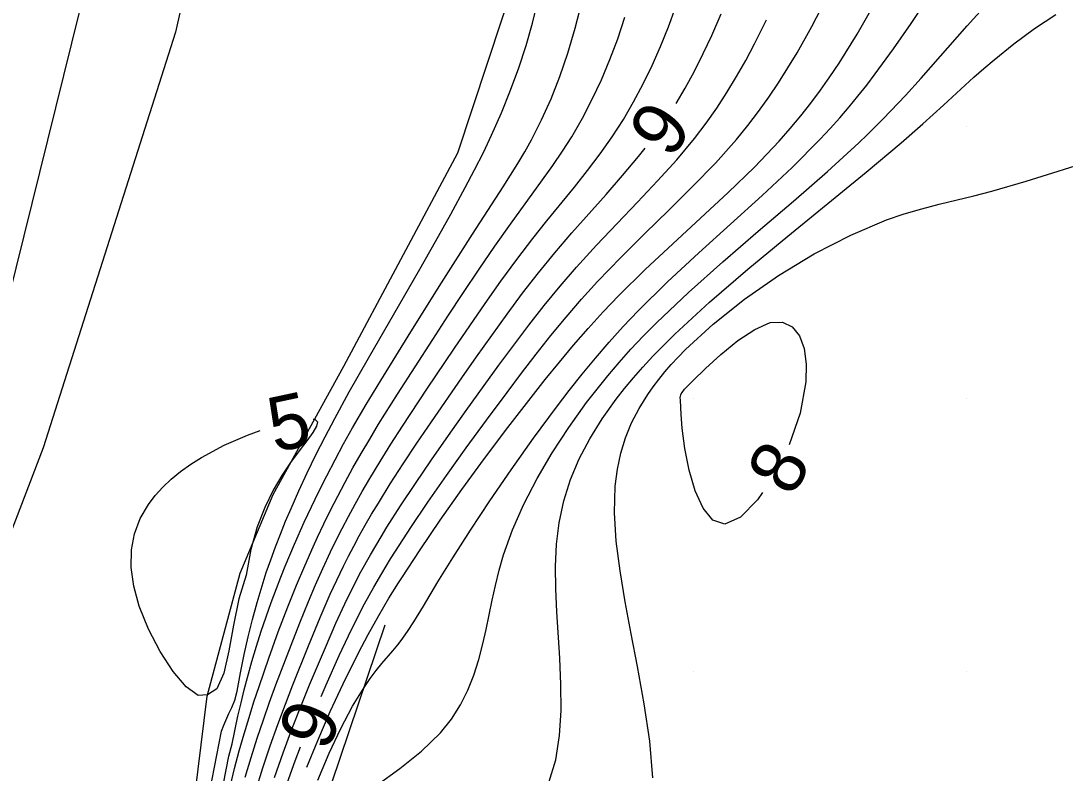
# Model space of a CAD drawing. Extents: x 2602990 to 2605851, y 618069 to 619180.
# Drawn here: x 2603415.29 to 2603453.62, y 618546.27 to 618573.87 of the extents above; entities that cross this region are included whole.
import ezdxf

# ---------------------------------------------------------------- set-up
doc = ezdxf.new("R2010")
doc.units = 0
for name, color, linetype in [('DTM Contours Major', 7, 'Continuous'), ('DTM Contours Major Text', 7, 'Continuous'), ('DTM Contours Minor', 7, 'Continuous'), ('DTM Contours Minor Text', 7, 'Continuous'), ('Exist DTM Crownline', 7, 'Continuous'), ('Exist DTM QL2 LIDAR Elevation Point', 7, 'Continuous'), ('Exist Roads EOP', 7, 'Continuous'), ('PH Exist DTM Breakline', 7, 'Continuous'), ('PH Exist DTM Obscure Area', 7, 'Continuous')]:
    doc.layers.add(name, color=color, linetype=linetype)

msp = doc.modelspace()

# ---------------------------------------------------------------- linework, layer by layer
at = {"layer": 'DTM Contours Major'}
for points in [[(2603439.345, 618570.846), (2603439.676, 618571.405), (2603440.018, 618572.033), (2603440.342, 618572.676), (2603440.652, 618573.336), (2603440.998, 618574.125)], [(2603423.915, 618545.634), (2603424.177, 618546.464), (2603424.449, 618547.269), (2603424.727, 618548.047), (2603425.006, 618548.793), (2603425.281, 618549.505), (2603425.849, 618550.933), (2603426.28, 618551.979), (2603426.65, 618552.831), (2603426.886, 618553.346), (2603427.136, 618553.864), (2603427.319, 618554.226), (2603427.512, 618554.597), (2603427.717, 618554.976), (2603427.936, 618555.365), (2603428.168, 618555.766), (2603428.416, 618556.18), (2603428.853, 618556.881), (2603429.327, 618557.614), (2603429.833, 618558.375), (2603430.364, 618559.158), (2603431.477, 618560.768), (2603432.023, 618561.549), (2603432.576, 618562.33), (2603433.139, 618563.107), (2603433.712, 618563.875), (2603434.297, 618564.629), (2603434.895, 618565.364), (2603435.519, 618566.092), (2603436.772, 618567.502), (2603437.38, 618568.197), (2603437.962, 618568.893), (2603438.204, 618569.205)]]:
    msp.add_lwpolyline(points, dxfattribs=at)
at = {"layer": 'DTM Contours Minor'}
for points in [[(2603421.36, 618538.867), (2603422.93, 618546.892), (2603423.048, 618547.34), (2603423.263, 618548.355), (2603423.376, 618548.845), (2603423.494, 618549.32), (2603423.615, 618549.783), (2603423.777, 618550.362), (2603423.944, 618550.925), (2603424.118, 618551.472), (2603424.298, 618552.007), (2603424.483, 618552.532), (2603424.675, 618553.047), (2603424.833, 618553.455), (2603424.995, 618553.86), (2603425.333, 618554.665), (2603425.695, 618555.474), (2603425.958, 618556.037), (2603426.234, 618556.607), (2603426.523, 618557.182), (2603426.825, 618557.763), (2603427.141, 618558.347), (2603427.47, 618558.936), (2603427.972, 618559.799), (2603428.504, 618560.681), (2603429.608, 618562.464), (2603430.737, 618564.26), (2603431.876, 618566.045), (2603432.997, 618567.777), (2603433.27, 618568.207), (2603433.534, 618568.636), (2603433.789, 618569.067), (2603434.033, 618569.505), (2603434.409, 618570.242), (2603434.756, 618571.014), (2603435.077, 618571.828), (2603435.372, 618572.691), (2603435.645, 618573.611), (2603435.896, 618574.596)], [(2603421.797, 618543.406), (2603422.659, 618547.806), (2603422.739, 618548.027), (2603422.926, 618548.451), (2603423.035, 618548.679), (2603423.151, 618548.943), (2603423.237, 618549.274), (2603423.357, 618549.954), (2603423.49, 618550.62), (2603423.635, 618551.271), (2603423.793, 618551.908), (2603423.963, 618552.532), (2603424.146, 618553.143), (2603424.303, 618553.625), (2603424.467, 618554.101), (2603424.64, 618554.572), (2603424.822, 618555.042), (2603425.012, 618555.51), (2603425.211, 618555.979), (2603425.5, 618556.629), (2603425.805, 618557.284), (2603426.126, 618557.944), (2603426.463, 618558.61), (2603426.815, 618559.281), (2603427.348, 618560.26), (2603428.048, 618561.495), (2603429.937, 618564.761), (2603430.514, 618565.771), (2603431.075, 618566.774), (2603431.608, 618567.755), (2603431.949, 618568.402), (2603432.271, 618569.039), (2603432.574, 618569.673), (2603432.939, 618570.5), (2603433.272, 618571.328), (2603433.572, 618572.154), (2603433.839, 618572.975), (2603434.073, 618573.787), (2603434.274, 618574.586)], [(2603425.792, 618546.485), (2603426.189, 618547.468), (2603426.648, 618548.525), (2603427.12, 618549.541), (2603427.686, 618550.677), (2603428.046, 618551.357), (2603428.434, 618552.053), (2603428.806, 618552.683), (2603429.151, 618553.245), (2603429.272, 618553.436), (2603429.945, 618554.468), (2603430.687, 618555.554), (2603431.481, 618556.675), (2603432.314, 618557.812), (2603433.168, 618558.946), (2603434.028, 618560.057), (2603434.544, 618560.708), (2603435.061, 618561.346), (2603435.585, 618561.971), (2603436.119, 618562.586), (2603436.669, 618563.192), (2603437.24, 618563.791), (2603438.21, 618564.747), (2603439.221, 618565.692), (2603440.245, 618566.631), (2603441.256, 618567.569), (2603442.227, 618568.51), (2603443.133, 618569.459), (2603443.537, 618569.918), (2603443.922, 618570.382), (2603444.292, 618570.852), (2603444.648, 618571.332), (2603444.993, 618571.821), (2603445.331, 618572.324), (2603445.995, 618573.384), (2603446.623, 618574.494)], [(2603426.189, 618546.011), (2603426.61, 618546.995), (2603427.041, 618547.907), (2603427.472, 618548.72), (2603427.891, 618549.41), (2603428.118, 618549.738), (2603428.338, 618550.028), (2603428.549, 618550.287), (2603428.943, 618550.75), (2603429.125, 618550.971), (2603429.249, 618551.129), (2603429.486, 618551.459), (2603429.722, 618551.818), (2603430.07, 618552.391), (2603430.601, 618553.282), (2603431.151, 618554.174), (2603431.793, 618555.178), (2603432.511, 618556.264), (2603433.288, 618557.4), (2603434.107, 618558.554), (2603434.951, 618559.695), (2603435.422, 618560.308), (2603435.899, 618560.909), (2603436.387, 618561.499), (2603436.888, 618562.082), (2603437.407, 618562.657), (2603437.947, 618563.227), (2603439.035, 618564.3), (2603440.179, 618565.362), (2603442.5, 618567.459), (2603443.608, 618568.495), (2603444.636, 618569.526), (2603445.003, 618569.922), (2603445.355, 618570.317), (2603445.694, 618570.714), (2603446.022, 618571.113), (2603446.342, 618571.516), (2603446.654, 618571.924), (2603447.328, 618572.844), (2603447.975, 618573.777), (2603448.596, 618574.712)], [(2603426.314, 618549.078), (2603426.497, 618549.505), (2603426.979, 618550.58), (2603427.321, 618551.311), (2603427.636, 618551.951), (2603427.912, 618552.484), (2603428.244, 618553.088), (2603428.54, 618553.598), (2603428.866, 618554.133), (2603429.041, 618554.413), (2603429.605, 618555.279), (2603430.235, 618556.211), (2603430.918, 618557.19), (2603431.64, 618558.199), (2603432.387, 618559.221), (2603433.144, 618560.24), (2603433.676, 618560.944), (2603434.211, 618561.638), (2603434.753, 618562.321), (2603435.306, 618562.994), (2603435.875, 618563.656), (2603436.464, 618564.307), (2603437.318, 618565.195), (2603438.198, 618566.068), (2603439.083, 618566.931), (2603439.953, 618567.791), (2603440.786, 618568.652), (2603441.562, 618569.52), (2603441.978, 618570.029), (2603442.371, 618570.544), (2603442.745, 618571.067), (2603443.103, 618571.599), (2603443.449, 618572.144), (2603443.784, 618572.702), (2603444.329, 618573.667), (2603444.847, 618574.67)], [(2603423.527, 618546.115), (2603423.743, 618546.844), (2603423.966, 618547.547), (2603424.195, 618548.225), (2603424.425, 618548.877), (2603424.655, 618549.504), (2603425.21, 618550.968), (2603425.531, 618551.784), (2603425.849, 618552.564), (2603426.107, 618553.174), (2603426.375, 618553.778), (2603426.659, 618554.387), (2603426.866, 618554.814), (2603427.085, 618555.247), (2603427.317, 618555.69), (2603427.563, 618556.142), (2603427.824, 618556.604), (2603428.1, 618557.078), (2603428.477, 618557.698), (2603428.878, 618558.337), (2603429.301, 618558.994), (2603430.199, 618560.354), (2603431.214, 618561.866), (2603431.771, 618562.686), (2603432.338, 618563.505), (2603432.914, 618564.318), (2603433.498, 618565.115), (2603434.089, 618565.89), (2603434.6, 618566.532), (2603435.61, 618567.774), (2603436.097, 618568.385), (2603436.563, 618568.998), (2603437.002, 618569.62), (2603437.409, 618570.251), (2603437.786, 618570.898), (2603438.137, 618571.56), (2603438.464, 618572.24), (2603438.772, 618572.938), (2603439.062, 618573.654), (2603439.327, 618574.361)], [(2603428.358, 618545.827), (2603429.205, 618546.44), (2603430.002, 618547.077), (2603430.695, 618547.748), (2603431.098, 618548.249), (2603431.431, 618548.77), (2603431.703, 618549.308), (2603431.924, 618549.863), (2603432.106, 618550.432), (2603432.256, 618551.013), (2603432.373, 618551.537), (2603432.592, 618552.609), (2603432.711, 618553.157), (2603432.848, 618553.713), (2603433.011, 618554.277), (2603433.342, 618555.201), (2603433.755, 618556.138), (2603434.241, 618557.08), (2603434.793, 618558.021), (2603435.402, 618558.952), (2603436.061, 618559.868), (2603436.443, 618560.363), (2603436.84, 618560.852), (2603437.254, 618561.338), (2603437.687, 618561.822), (2603438.142, 618562.307), (2603438.62, 618562.793), (2603439.795, 618563.907), (2603441.056, 618565.03), (2603442.36, 618566.15), (2603443.658, 618567.258), (2603444.906, 618568.344), (2603446.057, 618569.397), (2603446.363, 618569.692), (2603446.946, 618570.274), (2603447.497, 618570.85), (2603447.763, 618571.136), (2603448.338, 618571.773), (2603450.029, 618573.693), (2603450.613, 618574.338)], [(2603434.676, 618545.927), (2603434.925, 618546.761), (2603435.067, 618547.647), (2603435.124, 618548.572), (2603435.12, 618549.523), (2603435.076, 618550.487), (2603434.969, 618552.189), (2603434.93, 618553.029), (2603434.922, 618553.856), (2603434.957, 618554.667), (2603435.05, 618555.457), (2603435.223, 618556.259), (2603435.471, 618557.038), (2603435.791, 618557.797), (2603436.179, 618558.539), (2603436.633, 618559.268), (2603437.147, 618559.988), (2603437.455, 618560.381), (2603437.782, 618560.774), (2603438.129, 618561.168), (2603438.496, 618561.564), (2603438.885, 618561.965), (2603439.296, 618562.371), (2603440.572, 618563.549), (2603441.975, 618564.758), (2603443.442, 618565.974), (2603446.323, 618568.321), (2603447.612, 618569.403), (2603448.402, 618570.094), (2603449.162, 618570.783), (2603450.277, 618571.802), (2603450.643, 618572.127), (2603451.015, 618572.446), (2603451.742, 618573.031), (2603452.501, 618573.588), (2603453.288, 618574.108)], [(2603422.876, 618545.353), (2603423.137, 618546.434), (2603423.31, 618547.083), (2603423.487, 618547.706), (2603423.668, 618548.306), (2603423.851, 618548.884), (2603424.036, 618549.441), (2603424.395, 618550.483), (2603424.744, 618551.448), (2603425.094, 618552.368), (2603425.416, 618553.171), (2603425.711, 618553.873), (2603426.022, 618554.575), (2603426.185, 618554.929), (2603426.419, 618555.422), (2603426.665, 618555.922), (2603426.924, 618556.429), (2603427.196, 618556.943), (2603427.483, 618557.465), (2603427.785, 618557.995), (2603428.099, 618558.527), (2603428.427, 618559.068), (2603429.124, 618560.18), (2603430.411, 618562.181), (2603430.97, 618563.038), (2603431.539, 618563.901), (2603432.115, 618564.759), (2603432.693, 618565.601), (2603433.269, 618566.416), (2603434.446, 618568.034), (2603434.819, 618568.56), (2603435.176, 618569.087), (2603435.516, 618569.622), (2603435.907, 618570.298), (2603436.27, 618570.994), (2603436.604, 618571.71), (2603436.914, 618572.45), (2603437.202, 618573.214), (2603437.469, 618574.004)], [(2603424.603, 618546.112), (2603424.919, 618547.01), (2603425.244, 618547.88), (2603425.572, 618548.716), (2603425.894, 618549.507), (2603426.472, 618550.884), (2603426.858, 618551.765), (2603427.188, 618552.481), (2603427.505, 618553.129), (2603427.778, 618553.65), (2603428.126, 618554.278), (2603428.517, 618554.943), (2603428.733, 618555.293), (2603429.229, 618556.072), (2603429.778, 618556.9), (2603430.37, 618557.767), (2603430.994, 618558.662), (2603431.641, 618559.574), (2603432.3, 618560.491), (2603432.842, 618561.237), (2603433.388, 618561.977), (2603433.942, 618562.709), (2603434.508, 618563.431), (2603435.088, 618564.14), (2603435.685, 618564.835), (2603436.423, 618565.646), (2603437.176, 618566.438), (2603437.928, 618567.22), (2603438.663, 618567.997), (2603439.367, 618568.776), (2603440.024, 618569.562), (2603440.444, 618570.114), (2603440.838, 618570.674), (2603441.21, 618571.244), (2603441.563, 618571.826), (2603441.901, 618572.42), (2603442.227, 618573.03), (2603442.668, 618573.907)], [(2603438.493, 618546.091), (2603438.379, 618547.436), (2603438.176, 618548.805), (2603437.923, 618550.177), (2603437.691, 618551.378), (2603437.472, 618552.552), (2603437.286, 618553.691), (2603437.151, 618554.784), (2603437.086, 618555.821), (2603437.111, 618556.793), (2603437.188, 618557.416), (2603437.315, 618558.009), (2603437.49, 618558.575), (2603437.714, 618559.119), (2603437.985, 618559.646), (2603438.303, 618560.159), (2603438.498, 618560.438), (2603438.707, 618560.714), (2603438.93, 618560.989), (2603439.168, 618561.264), (2603439.422, 618561.538), (2603439.69, 618561.813), (2603440.703, 618562.744), (2603441.855, 618563.66), (2603443.106, 618564.531), (2603444.418, 618565.326), (2603445.753, 618566.015), (2603447.072, 618566.568), (2603447.721, 618566.788), (2603448.361, 618566.976), (2603448.998, 618567.143), (2603450.277, 618567.458), (2603450.931, 618567.626), (2603452.19, 618567.991), (2603454.776, 618568.795)], [(2603439.658, 618560.357), (2603439.964, 618560.665), (2603440.426, 618561.117), (2603440.993, 618561.634), (2603441.612, 618562.139), (2603442.232, 618562.553), (2603442.799, 618562.799), (2603443.252, 618562.822), (2603443.609, 618562.65), (2603443.874, 618562.315), (2603444.044, 618561.846), (2603444.122, 618561.273), (2603444.108, 618560.627), (2603443.894, 618559.473), (2603443.492, 618558.312)], [(2603442.522, 618556.568), (2603442.338, 618556.294), (2603441.712, 618555.661), (2603441.131, 618555.407), (2603440.694, 618555.552), (2603440.334, 618555.986), (2603440.046, 618556.624), (2603439.826, 618557.383), (2603439.67, 618558.18), (2603439.573, 618558.931), (2603439.534, 618559.429), (2603439.503, 618559.951), (2603439.492, 618560.047), (2603439.517, 618560.147), (2603439.536, 618560.19), (2603439.564, 618560.235), (2603439.658, 618560.357)], [(2603426.022, 618559.261), (2603426.08, 618559.258), (2603426.176, 618559.162), (2603426.146, 618558.996), (2603426.01, 618558.763), (2603425.791, 618558.462), (2603425.512, 618558.096), (2603425.194, 618557.666), (2603424.872, 618557.191), (2603424.55, 618556.646), (2603424.243, 618556.02), (2603423.966, 618555.3), (2603423.733, 618554.474), (2603423.561, 618553.531), (2603423.293, 618552.659), (2603423.096, 618551.698), (2603422.926, 618550.756), (2603422.74, 618549.942), (2603422.493, 618549.366), (2603422.141, 618549.137)], [(2603422.141, 618549.137), (2603421.796, 618549.121), (2603421.363, 618549.433), (2603420.887, 618549.994), (2603420.411, 618550.726), (2603419.982, 618551.553), (2603419.641, 618552.394), (2603419.438, 618553.132), (2603419.346, 618553.819), (2603419.358, 618554.459), (2603419.47, 618555.054), (2603419.677, 618555.609), (2603419.974, 618556.126), (2603420.219, 618556.451), (2603420.5, 618556.761), (2603420.814, 618557.056), (2603421.157, 618557.336), (2603421.528, 618557.602), (2603421.924, 618557.852), (2603422.753, 618558.298), (2603423.608, 618558.675), (2603424.082, 618558.847)], [(2603420.388, 618514.415), (2603421.14, 618520.222), (2603421.506, 618523.149), (2603421.673, 618524.559), (2603421.872, 618526.338), (2603422.396, 618531.347), (2603422.68, 618533.914), (2603422.894, 618535.715), (2603423.014, 618536.664), (2603423.143, 618537.614), (2603423.282, 618538.561), (2603423.435, 618539.504), (2603423.603, 618540.439), (2603423.747, 618541.163), (2603423.903, 618541.882), (2603424.071, 618542.596), (2603424.254, 618543.307), (2603424.453, 618544.017), (2603424.668, 618544.725), (2603425.002, 618545.731), (2603425.362, 618546.725), (2603425.557, 618547.227)]]:
    msp.add_lwpolyline(points, dxfattribs=at)
at = {"layer": 'Exist DTM Crownline'}
msp.add_spline([(2603233.488, 618380.754), (2603285.185, 618400.095), (2603335.457, 618418.629), (2603390.812, 618439.069), (2603440.087, 618457.325), (2603493.996, 618477.231), (2603542.655, 618495.301), (2603600.808, 618516.867), (2603653.659, 618536.362), (2603706.222, 618555.742), (2603764.811, 618577.593), (2603823.52, 618599.847), (2603878.564, 618620.56), (2603937.951, 618643.078), (2603997.369, 618665.789), (2604036.209, 618680.665), (2604055.311, 618688.017)], degree=3, dxfattribs=at)
at = {"layer": 'Exist DTM QL2 LIDAR Elevation Point'}
for p, q in [((2603450, 618570), (2603450, 618570)), ((2603440, 618560), (2603440, 618560)), ((2603450, 618560), (2603450, 618560)), ((2603440, 618550), (2603440, 618550)), ((2603450, 618550), (2603450, 618550))]:
    msp.add_line(p, q, dxfattribs=at)
at = {"layer": 'Exist Roads EOP'}
for points in [[(2603230.17, 618389.98), (2603282.929, 618409.597), (2603332.773, 618427.868), (2603388.167, 618448.413), (2603437.203, 618466.721), (2603490.778, 618486.527), (2603539.039, 618504.558), (2603597.451, 618526.156), (2603651.053, 618545.972), (2603705.208, 618566.084), (2603762.02, 618587.183), (2603820.334, 618609.162), (2603876.341, 618629.99), (2603934.909, 618652.28), (2603996.409, 618675.568), (2604033.216, 618689.957), (2604052.01, 618697.199)], [(2604034.633, 618668.486), (2603984.89, 618650.123), (2603936.767, 618631.654), (2603888.195, 618613.335), (2603837.766, 618594.258), (2603782.918, 618573.705), (2603731.939, 618554.39), (2603671.126, 618532.171), (2603621.822, 618514.106), (2603561.545, 618491.877), (2603506.421, 618471.293), (2603452.163, 618451.33), (2603398.364, 618431.316), (2603341.431, 618410.355), (2603281.65, 618388.199), (2603223.033, 618366.475), (2603185.717, 618352.612)]]:
    msp.add_spline(points, degree=3, dxfattribs=at)
at = {"layer": 'PH Exist DTM Breakline'}
for points in [[(2603420.106, 618512.049), (2603420.211, 618516.533), (2603420.648, 618529.041), (2603420.819, 618538.47), (2603422.128, 618549.088), (2603423.344, 618553.609), (2603424.552, 618556.495), (2603427.152, 618561.197), (2603431.339, 618569.035), (2603433.508, 618575.626), (2603437.546, 618591.762), (2603439.238, 618603.824), (2603439.585, 618610.612), (2603438.591, 618626.145), (2603435.827, 618639.611), (2603430.526, 618661.513), (2603425.292, 618684.296), (2603417.979, 618715.577)], [(2603408.22, 618711.909), (2603415.864, 618676.266), (2603422.019, 618648.891), (2603426.776, 618631.517), (2603427.443, 618626.233), (2603427.478, 618620.512), (2603427.295, 618608.569), (2603425.141, 618592.108), (2603420.965, 618573.458), (2603416.114, 618558.205), (2603413.059, 618550.236), (2603411.173, 618537.294), (2603410.55, 618525.353), (2603410.291, 618510.77), (2603410.807, 618500.206), (2603412.958, 618489.948), (2603414.564, 618484.094), (2603414.609, 618480.322), (2603413.96, 618476.113), (2603411.856, 618470.088), (2603407.732, 618462.124), (2603403.683, 618456.863), (2603402.289, 618454.592)], [(2603433.996, 618481.025), (2603430.516, 618485.883), (2603428.217, 618490.776), (2603427.219, 618496.134), (2603425.266, 618507.559), (2603424.877, 618516.733), (2603424.982, 618530.313), (2603425.392, 618542.002), (2603428.667, 618551.709)]]:
    msp.add_lwpolyline(points, dxfattribs=at)
at = {"layer": 'PH Exist DTM Obscure Area'}
msp.add_lwpolyline([(2603414.824, 618563.614), (2603418.913, 618580.137), (2603421.794, 618598.652), (2603418.146, 618605.332), (2603415.062, 618610.55)], dxfattribs=at)

# ---------------------------------------------------------------- texts
at = {"layer": 'DTM Contours Major Text'}
msp.add_text('6', height=2, rotation=235.1838, dxfattribs=at).set_placement((2603438.35, 618571.116))
at = {"layer": 'DTM Contours Minor Text'}
for s, rotation, p in [('5', 12.028, (2603424.605, 618558.03)), ('8', 60.9076, (2603443.608, 618556.357)), ('6', 247.7426, (2603425.249, 618549.139))]:
    msp.add_text(s, height=2, rotation=rotation, dxfattribs=at).set_placement(p)

doc.saveas('drawing.dxf')
